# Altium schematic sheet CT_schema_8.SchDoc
size 254 x 194 mm
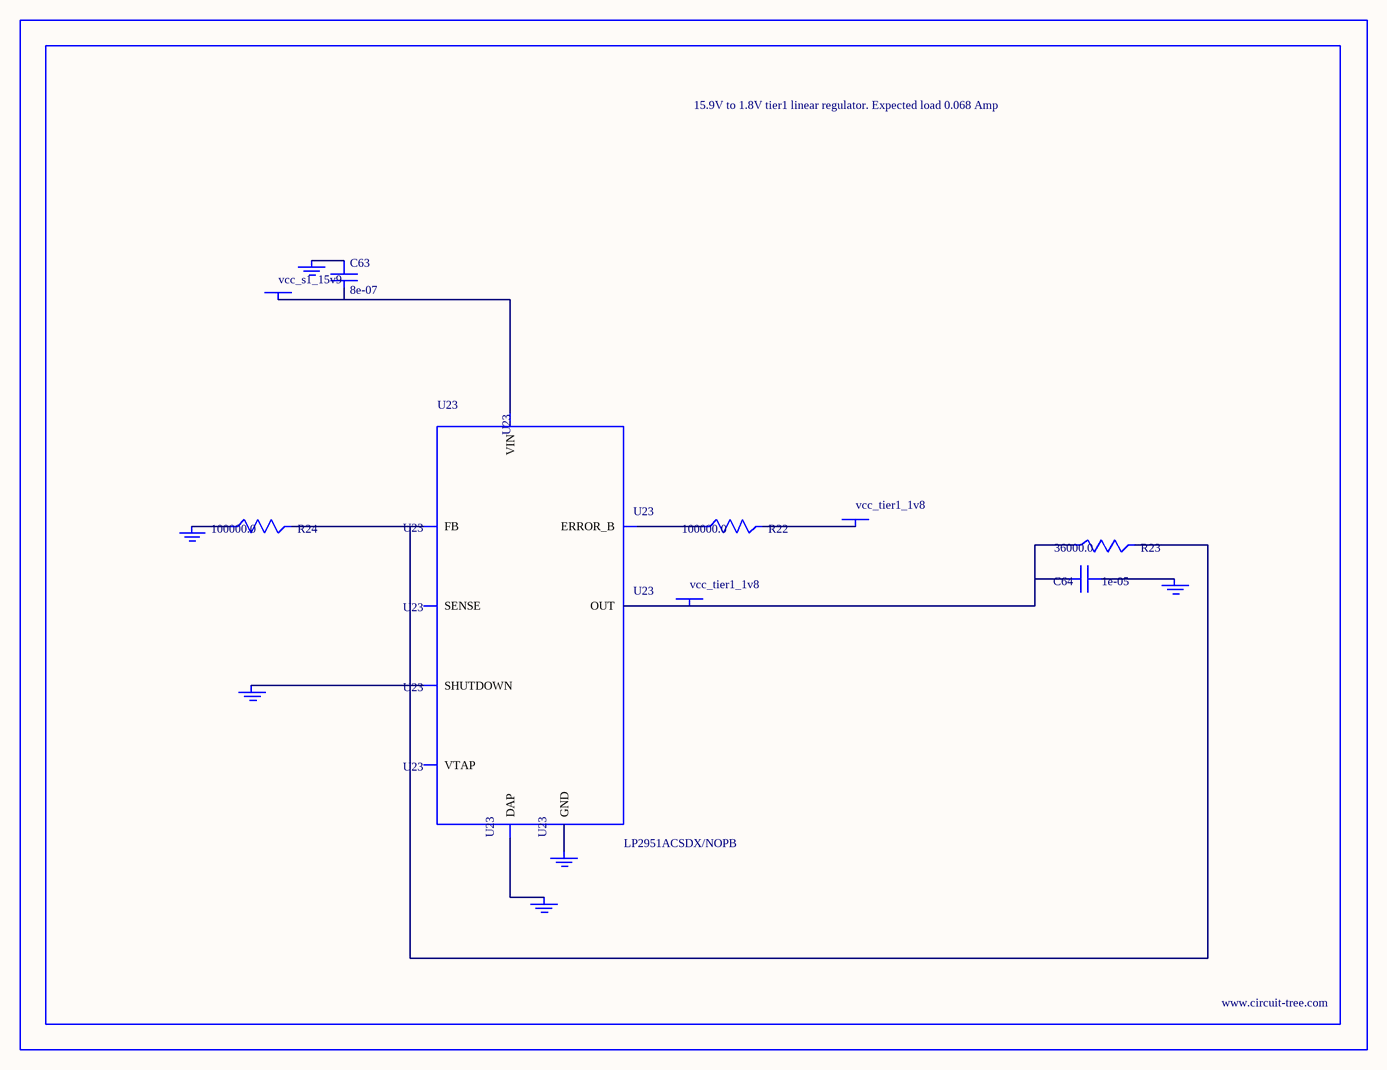
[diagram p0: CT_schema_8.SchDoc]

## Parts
BORDER7  (no value)
C63  8e-07  [R0603]
C64  1e-05  [C0805]
GND_INSTANCE_7_0  (no value)
GND_INSTANCE_7_1  (no value)
GND_INSTANCE_7_2  (no value)
GND_INSTANCE_7_3  (no value)
GND_INSTANCE_7_4  (no value)
GND_INSTANCE_7_5  (no value)
POWER_INSTANCE_7_0  vcc_tier1_1v8
POWER_INSTANCE_7_1  vcc_s1_15v9
POWER_INSTANCE_7_2  vcc_tier1_1v8
R22  100000.0  [R0603]
R23  36000.0  [R0603]
R24  100000.0  [R0603]
U23  LP2951ACSDX/NOPB  [WSON-8]

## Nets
NetC63_1: C63.1 GND_INSTANCE_7_3.0(GND)
NetC63_2: C63.2 POWER_INSTANCE_7_1.0(PWR) U23.8(VIN)
NetC64_1: C64.1 GND_INSTANCE_7_0.0(GND)
NetC64_2: C64.2 POWER_INSTANCE_7_2.0(PWR) R23.1 U23.1(OUT)
NetGND_INSTANCE_7_1_0: GND_INSTANCE_7_1.0(GND) U23.3(SHUTDOWN)
NetGND_INSTANCE_7_2_0: GND_INSTANCE_7_2.0(GND) R24.1
NetGND_INSTANCE_7_4_0: GND_INSTANCE_7_4.0(GND) U23.PAD(DAP)
NetGND_INSTANCE_7_5_0: GND_INSTANCE_7_5.0(GND) U23.4(GND)
NetPOWER_INSTANCE_7_0_0: POWER_INSTANCE_7_0.0(PWR) R22.2
NetR22_1: R22.1 U23.5(ERROR_B)
NetR23_2: R23.2 R24.2 U23.7(FB)

Not connected (* = marked no-connect by the designer): U23 2(SENSE) 6(VTAP)

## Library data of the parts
BORDER7 = BORDER_PAGE7
C63 = C63
C64 = GRM219R60J106ME19D
GND_INSTANCE_7_0-GND_INSTANCE_7_5 = GND
POWER_INSTANCE_7_0-POWER_INSTANCE_7_2 = PWR
R22 R24 = RC0603JR-07100KL
R23 = RC0603JR-0736KL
